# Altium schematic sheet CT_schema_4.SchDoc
size 289 x 230 mm
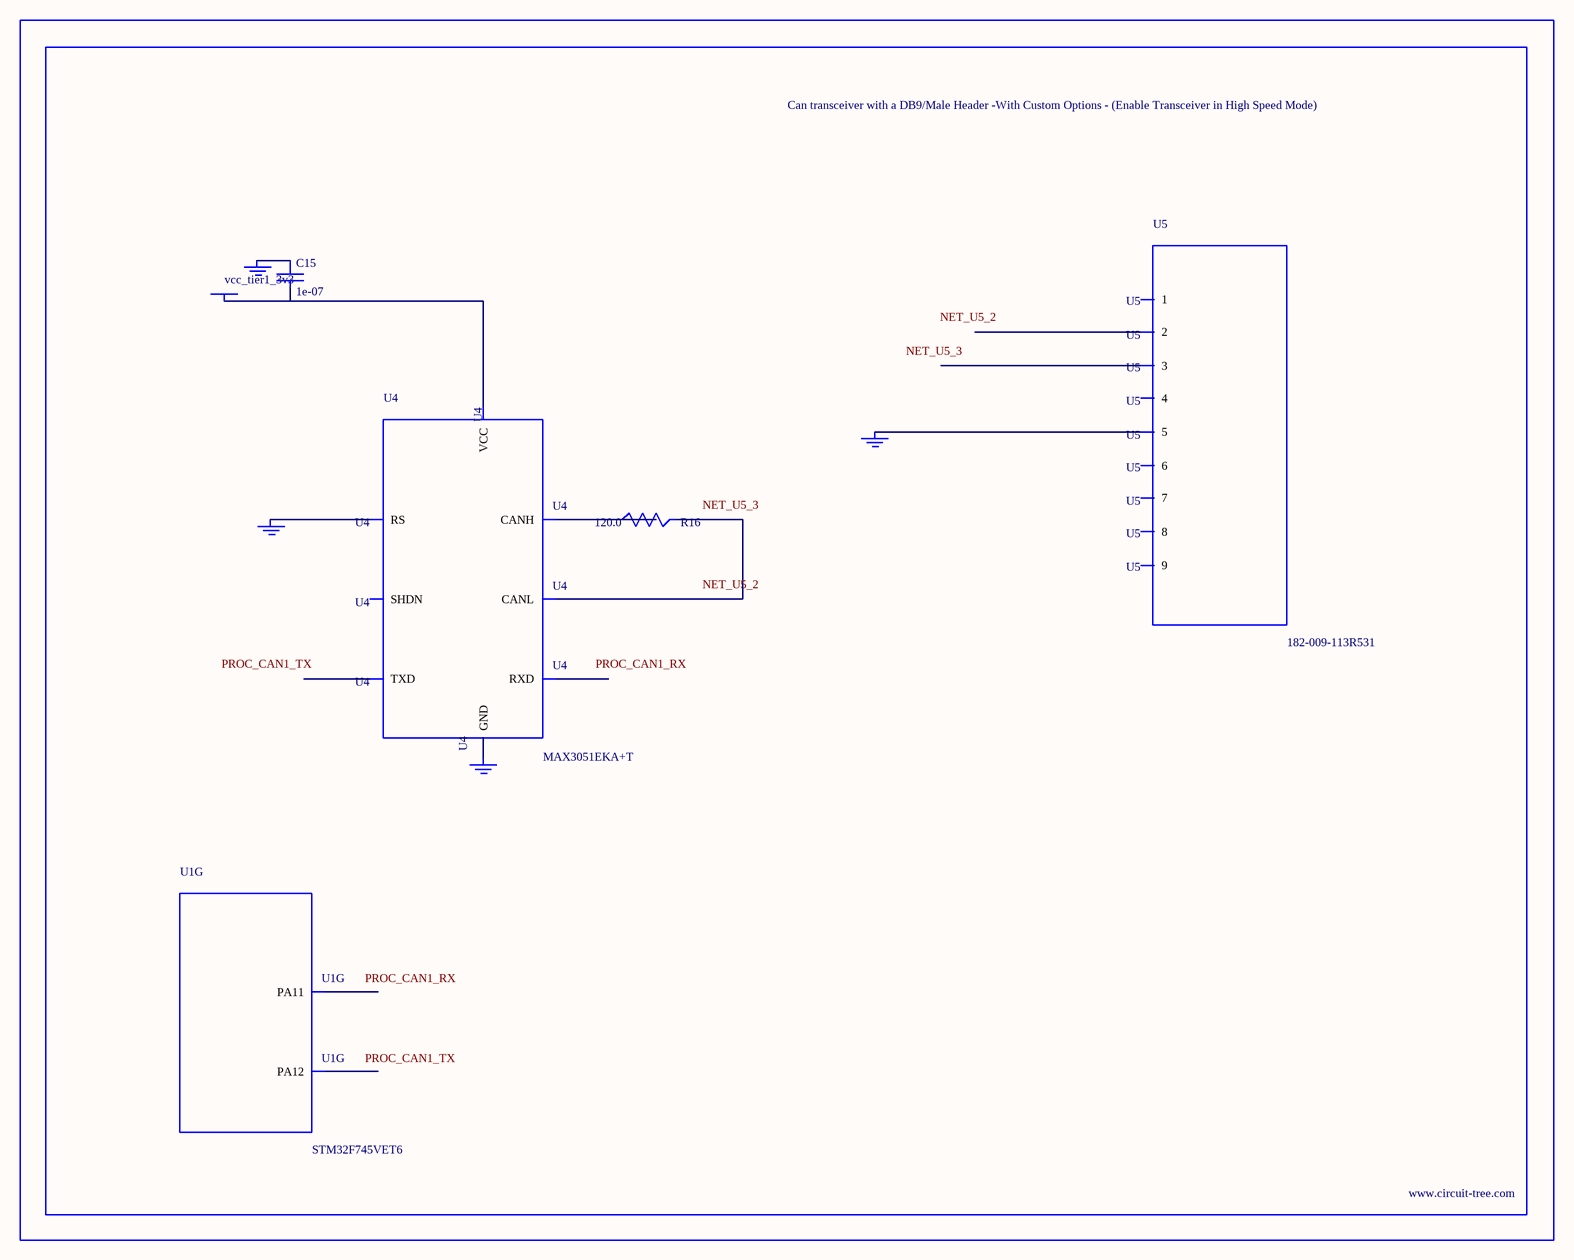
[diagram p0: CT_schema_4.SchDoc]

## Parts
BORDER3  (no value)
C15  1e-07  [C0402]
GND_INSTANCE_3_0  (no value)
GND_INSTANCE_3_1  (no value)
GND_INSTANCE_3_2  (no value)
GND_INSTANCE_3_3  (no value)
POWER_INSTANCE_3_0  vcc_tier1_3v3
R16  120.0  [R0603]
U1  STM32F745VET6  [LQFP100]  (part G of 9)
U4  MAX3051EKA+T  [SOT-23-8]
U5  182-009-113R531  [182-009-MALE]

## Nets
NetC15_1: C15.1 GND_INSTANCE_3_0.0(GND)
NetC15_2: C15.2 POWER_INSTANCE_3_0.0(PWR) U4.3(VCC)
NetGND_INSTANCE_3_1_0: GND_INSTANCE_3_1.0(GND) U4.8(RS)
NetGND_INSTANCE_3_2_0: GND_INSTANCE_3_2.0(GND) U4.2(GND)
NetGND_INSTANCE_3_3_0: GND_INSTANCE_3_3.0(GND) U5.5
NetR16_1: R16.1 U4.7(CANH)
NetR16_2: R16.2 U4.6(CANL)

Not connected (* = marked no-connect by the designer): U1 70(PA11) 71(PA12); U4 1(TXD) 4(RXD) 5(SHDN); U5 1 2 3 4 6 7 8 9

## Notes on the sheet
- Labels drawn without touching a wire or pin: NET_U5_2, NET_U5_3, PROC_CAN1_RX, PROC_CAN1_TX

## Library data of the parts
BORDER3 = BORDER_PAGE3
C15 = C0402C104K3RACTU
GND_INSTANCE_3_0-GND_INSTANCE_3_3 = GND
POWER_INSTANCE_3_0 = PWR
R16 = RC0603JR-07120RL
